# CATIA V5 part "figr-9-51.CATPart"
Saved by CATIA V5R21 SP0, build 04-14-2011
Part number: Part1
Bounding box of the stored display mesh (mm): x -121 to 121, y -90 to 90, z -40 to 40
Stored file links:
  D:\CATIA V5R21 E-RESOURCES\CATIA-V5R21\catia-v5r21-prt\c09-catia-v5r20-prt\c09-catia-v5r21-figr-9-51.CATPart
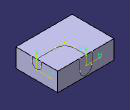
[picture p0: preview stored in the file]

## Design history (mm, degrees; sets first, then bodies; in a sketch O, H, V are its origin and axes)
Body1 (main body)
  Sketch1 on yz-plane, origin (0, 0, 0), H (0, 1, 0), V (0, 0, 1)
    line L1 (-90, 40) -> (90, 40)
    line L2 (90, 40) -> (90, -40)
    line L3 (90, -40) -> (-90, -40)
    line L4 (-90, -40) -> (-90, 40)
    axis line L5 (90, -40) -> (-90, 40)
    horizontal: L1 H, L3 H
    vertical: L2 V, L4 V
    midpoint: O L5
  Pad1: profile Sketch1, direction (1, 0, 0), length 121, mirrored extent
  Sketch2 on face of Pad1, origin (0, 0, 40), H (1, 0, 0), V (0, 1, 0)
    point P1 (121, 0)
    line L1 (121, 0) -> (40.984, 0)
    arc A1 centre (40.984, 40.984) radius 40.984 from (40.984, 0) to (0, 40.984) cw
    line L2 (0, 40.984) -> (0, 90)
    point P5 (0, 90)
    reference projected line E1 (121, 20) -> (121, -20) from edge of Sketch4
    reference projected line E2 (-25.9516, 90) -> (25.9516, 90) from edge of Sketch3
    coincidence: P1 H, P1 E1, P5 E2
    horizontal: L1 H
    tangency: A1 L1, L2 A1
    vertical: L2 V
  Sketch3 on face of Pad1, origin (0, 90, 0), H (-1, 0, 0), V (0, 0, 1)
    line L1 (-25.9516, 40) -> (-25.9516, -8.0968)
    arc A1 centre (0, -8.0968) radius 25.9516 from (-25.9516, -8.0968) to (25.9516, -8.0968) ccw
    point P3 (0, -8.0968)
    line L2 (25.9516, -8.0968) -> (25.9516, 40)
    line L3 (25.9516, 40) -> (-25.9516, 40)
    reference projected line E1 (121, 40) -> (-121, 40) from edge [face of Pad1 | face of Pad1]
    vertical: L1 V, L2 V
    tangency: A1 L1, L2 A1
    horizontal: L3 H
    coincidence: P3 V, L3 E1
  Sketch4 on face of Pad1, origin (121, 0, 0), H (0, 1, 0), V (0, 0, 1)
    line L1 (-20, 40) -> (-20, 21.9917)
    arc A1 centre (0, 21.9917) radius 20 from (-20, 21.9917) to (20, 21.9917) ccw
    point P3 (0, 21.9917)
    line L2 (20, 21.9917) -> (20, 40)
    line L3 (20, 40) -> (-20, 40)
    reference projected line E1 (90, 40) -> (-90, 40) from edge [face of Pad1 | face of Pad1]
    vertical: L1 V, L2 V
    tangency: A1 L1, L2 A1
    horizontal: L3 H
    coincidence: P3 V, L3 E1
